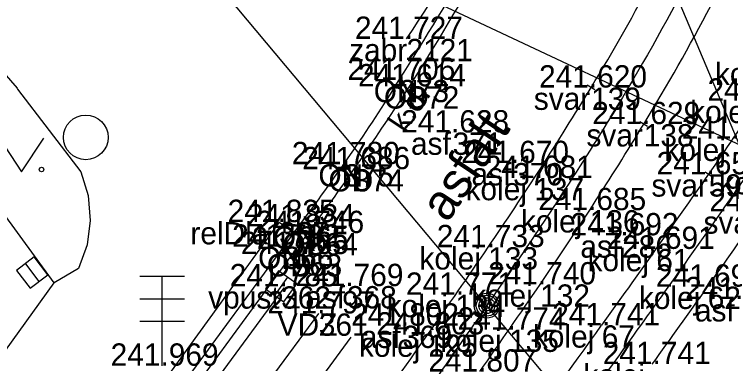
# Model space of a CAD drawing. Extents: x -599098 to -598820, y -1159597 to -1158744.
# Drawn here: x -598917.65 to -598901.61, y -1159373.2 to -1159365.37 of the extents above; entities that cross this region are included whole.
import ezdxf

# ---------------------------------------------------------------- set-up
doc = ezdxf.new("R2010")
doc.units = 0
for name, color, linetype in [('body', 7, 'Continuous'), ('dešťové vpusti šachty', 7, 'Continuous'), ('dopravní značky semafory', 7, 'Continuous'), ('druh pozemku stromy', 7, 'Continuous'), ('kresba', 7, 'Continuous'), ('kódy bodů', 7, 'Continuous'), ('popisy', 7, 'Continuous'), ('tram_detaily', 7, 'Continuous'), ('tram_koleje', 7, 'Continuous'), ('tram_osa', 7, 'Continuous'), ('trol_detaily', 7, 'Continuous'), ('trol_převěsy', 7, 'Continuous'), ('vodorovné dopravní značení_bílé', 7, 'Continuous'), ('výšky bodů', 7, 'Continuous'), ('značky IS', 7, 'Continuous'), ('zábradlí', 7, 'Continuous'), ('čísla bodů', 7, 'Continuous')]:
    doc.layers.add(name, color=color, linetype=linetype)

msp = doc.modelspace()

# ---------------------------------------------------------------- linework, layer by layer
at = {"layer": 'body'}
for p, q in [((-598908.871, -1159365.923), (-598908.871, -1159365.923)), ((-598909.033, -1159366.841), (-598909.033, -1159366.841)), ((-598908.803, -1159366.986), (-598908.803, -1159366.986)), ((-598904.736, -1159367.013), (-598904.736, -1159367.013)), ((-598903.558, -1159367.833), (-598903.558, -1159367.833)), ((-598907.837, -1159368.02), (-598907.837, -1159368.02)), ((-598906.482, -1159368.705), (-598906.482, -1159368.705)), ((-598910.272, -1159368.73), (-598910.272, -1159368.73)), ((-598910.045, -1159368.842), (-598910.045, -1159368.842)), ((-598902.103, -1159368.956), (-598902.103, -1159368.956)), ((-598906.008, -1159369.038), (-598906.008, -1159369.038)), ((-598904.768, -1159369.76), (-598904.768, -1159369.76)), ((-598911.722, -1159370.026), (-598911.722, -1159370.026)), ((-598911.292, -1159370.125), (-598911.292, -1159370.125)), ((-598911.074, -1159370.273), (-598911.074, -1159370.273)), ((-598904.044, -1159370.324), (-598904.044, -1159370.324)), ((-598911.622, -1159370.578), (-598911.622, -1159370.578)), ((-598907.04, -1159370.59), (-598907.04, -1159370.59)), ((-598903.277, -1159370.628), (-598903.277, -1159370.628)), ((-598911.425, -1159370.744), (-598911.425, -1159370.744)), ((-598905.877, -1159371.424), (-598905.877, -1159371.424)), ((-598911.675, -1159371.466), (-598911.675, -1159371.466)), ((-598910.203, -1159371.461), (-598910.203, -1159371.461)), ((-598902.126, -1159371.474), (-598902.126, -1159371.474)), ((-598907.774, -1159371.656), (-598907.774, -1159371.656)), ((-598910.833, -1159372.075), (-598910.833, -1159372.075)), ((-598908.959, -1159372.348), (-598908.959, -1159372.348)), ((-598904.5, -1159372.34), (-598904.5, -1159372.34)), ((-598908.394, -1159372.546), (-598908.394, -1159372.546)), ((-598906.574, -1159372.436), (-598906.574, -1159372.436))]:
    msp.add_line(p, q, dxfattribs=at)
at = {"layer": 'dešťové vpusti šachty'}
msp.add_line((-598911.821, -1159371.669), (-598911.529, -1159371.263), dxfattribs=at)
msp.add_lwpolyline([(-598911.618, -1159371.815), (-598911.326, -1159371.409), (-598911.732, -1159371.117), (-598912.024, -1159371.523)], close=True, dxfattribs=at)
at = {"layer": 'dopravní značky semafory'}
for p, q in [((-598913.842, -1159371.245), (-598914.842, -1159371.245)), ((-598914.342, -1159373.245), (-598914.342, -1159371.245)), ((-598914.842, -1159371.745), (-598913.842, -1159371.745)), ((-598914.842, -1159372.245), (-598913.842, -1159372.245))]:
    msp.add_line(p, q, dxfattribs=at)
at = {"layer": 'druh pozemku stromy'}
msp.add_lwpolyline([(-598917.99, -1159368.15), (-598917.49, -1159368.9), (-598916.99, -1159368.15)], dxfattribs=at)
msp.add_circle((-598917.041, -1159368.85), 0.05, dxfattribs=at)
at = {"layer": 'kresba'}
for p, q in [((-598917.58, -1159367.05), (-598916.16, -1159368.9)), ((-598911.722, -1159370.026), (-598915.873, -1159375.751)), ((-598911.722, -1159370.026), (-598911.393, -1159370.264)), ((-598911.292, -1159370.125), (-598911.622, -1159370.578)), ((-598911.425, -1159370.744), (-598911.074, -1159370.273)), ((-598911.622, -1159370.578), (-598914.322, -1159374.262)), ((-598914.091, -1159374.398), (-598911.425, -1159370.744))]:
    msp.add_line(p, q, dxfattribs=at)
for points in [[(-598919.1, -1159366.24), (-598918.51, -1159366.31), (-598917.99, -1159366.57), (-598917.59, -1159367.03), (-598917.58, -1159367.05)], [(-598937.39, -1159400.08), (-598916.76, -1159371.39), (-598918.73, -1159368.69)], [(-598916.16, -1159368.9), (-598916, -1159369.43), (-598915.95, -1159369.99), (-598916.02, -1159370.54), (-598916.21, -1159371.07), (-598916.76, -1159371.39)]]:
    msp.add_lwpolyline(points, dxfattribs=at)
for centre, radius, start, end in [((-598969.883, -1159328.28), 72.04, 327.63743, 330.28134), ((-598951.766, -1159339.58), 50.96, 327.4658, 331.2241), ((-598942.435, -1159346.283), 39.221, 322.564, 328.3893), ((-598958.726, -1159334.922), 59.333, 323.42989, 327.28864)]:
    msp.add_arc(centre, radius, start, end, dxfattribs=at)
at = {"layer": 'tram_detaily'}
for p, q in [((-598904.65, -1159367.064), (-598904.823, -1159366.963)), ((-598903.471, -1159367.883), (-598903.645, -1159367.782)), ((-598902.186, -1159368.9), (-598902.021, -1159369.013))]:
    msp.add_line(p, q, dxfattribs=at)
at = {"layer": 'tram_koleje'}
for centre, radius, start, end in [((-598942.625, -1159343.975), 44.343, 328.6991, 336.177), ((-598943.054, -1159343.749), 46.26, 328.6262, 336.1731), ((-598974.788, -1159324.422), 81.983, 325.72685, 328.70075), ((-599014.099, -1159291.363), 136.248, 325.28506, 326.12393), ((-598970.789, -1159326.961), 78.68, 325.58976, 328.70301), ((-599111.282, -1159223.328), 254.879, 324.22268, 325.1549), ((-599144.2, -1159199.597), 296.887, 324.21267, 325.02292), ((-599086.951, -1159247.497), 217.991, 324.99526, 325.62053), ((-599085.463, -1159248.483), 217.636, 324.98007, 325.60519), ((-600445.718, -1158261.326), 1899.922, 323.996025, 324.213389), ((-599082.727, -1159250.878), 212.591, 324.37258, 325.08858)]:
    msp.add_arc(centre, radius, start, end, dxfattribs=at)
at = {"layer": 'tram_osa'}
for points in [[(-598908.157, -1159378.609), (-598907.552, -1159377.778), (-598906.868, -1159376.836), (-598906.259, -1159375.995), (-598905.722, -1159375.252), (-598905.236, -1159374.581), (-598903.934, -1159372.775), (-598902.701, -1159371.051), (-598901.52, -1159369.371), (-598900.942, -1159368.531), (-598900.379, -1159367.695), (-598899.817, -1159366.835), (-598899.27, -1159365.964), (-598898.407, -1159364.472), (-598897.213, -1159362.023), (-598896.143, -1159359.185), (-598895.328, -1159356.139), (-598894.957, -1159354.036), (-598894.725, -1159351.774), (-598894.664, -1159349.708), (-598894.744, -1159347.678), (-598894.942, -1159345.779), (-598895.289, -1159343.649), (-598895.717, -1159341.566), (-598895.998, -1159340.38), (-598896.298, -1159339.199), (-598896.678, -1159337.758), (-598897.069, -1159336.322), (-598897.39, -1159335.158), (-598897.753, -1159333.858), (-598898.122, -1159332.54), (-598898.277, -1159331.985), (-598898.513, -1159331.142), (-598898.836, -1159329.985), (-598899.092, -1159329.068)], [(-598901.994, -1159329.852), (-598901.845, -1159330.39), (-598901.631, -1159331.17), (-598901.437, -1159331.875), (-598901.198, -1159332.751), (-598900.91, -1159333.821), (-598900.692, -1159334.638), (-598900.522, -1159335.294), (-598900.329, -1159336.063), (-598900.132, -1159336.868), (-598899.889, -1159337.918), (-598899.746, -1159338.571), (-598899.547, -1159339.551), (-598899.39, -1159340.382), (-598899.195, -1159341.532), (-598899.02, -1159342.683), (-598898.837, -1159344.035), (-598898.771, -1159344.588), (-598898.665, -1159345.59), (-598898.593, -1159346.409), (-598898.554, -1159347.04), (-598898.521, -1159347.953), (-598898.531, -1159349.751), (-598898.642, -1159351.517), (-598898.931, -1159353.817), (-598899.252, -1159355.498), (-598899.926, -1159358.17), (-598900.833, -1159360.806), (-598901.398, -1159362.161), (-598902.424, -1159364.327), (-598904.147, -1159367.423), (-598905.388, -1159369.399), (-598906.458, -1159371.007), (-598907.174, -1159372.046), (-598907.418, -1159372.398), (-598907.811, -1159372.961), (-598908.189, -1159373.5), (-598908.527, -1159373.98), (-598908.94, -1159374.563), (-598909.247, -1159374.993), (-598909.701, -1159375.623), (-598910.021, -1159376.065), (-598910.194, -1159376.303), (-598910.561, -1159376.808)]]:
    msp.add_spline(points, degree=3, dxfattribs=at)
at = {"layer": 'trol_detaily'}
for radius in [0.28, 0.235, 0.178, 0.118, 0.0641]:
    msp.add_circle((-598907.072, -1159371.9), radius, dxfattribs=at)
at = {"layer": 'trol_převěsy'}
for p, q in [((-598906.25, -1159356.79), (-598900.24, -1159371.111)), ((-598900.99, -1159379.16), (-598915.7, -1159361.6)), ((-598894.78, -1159371.42), (-598915.68, -1159361.59))]:
    msp.add_line(p, q, dxfattribs=at)
at = {"layer": 'vodorovné dopravní značení_bílé'}
for p, q in [((-598914.607, -1159375.572), (-598911.608, -1159371.5)), ((-598913.832, -1159376.147), (-598910.833, -1159372.075)), ((-598913.104, -1159376.676), (-598910.105, -1159372.604))]:
    msp.add_line(p, q, dxfattribs=at)
at = {"layer": 'značky IS'}
msp.add_line((-598917.403, -1159370.962), (-598917.1, -1159371.359), dxfattribs=at)
msp.add_lwpolyline([(-598917.601, -1159371.114), (-598917.298, -1159371.511), (-598916.9, -1159371.207), (-598917.205, -1159370.809)], close=True, dxfattribs=at)
msp.add_circle((-598916.05, -1159368.13), 0.5, dxfattribs=at)
at = {"layer": 'zábradlí'}
msp.add_arc((-598931.603, -1159350.423), 27.513, 325.7123, 341.6416, dxfattribs=at)

# ---------------------------------------------------------------- texts
at = {"layer": 'kódy bodů'}
for s, p in [('zabr', (-598910.154, -1159366.423)), ('kolej', (-598901.964, -1159366.958)), ('ON', (-598909.603, -1159367.341)), ('OD', (-598909.375, -1159367.486)), ('svar', (-598906.019, -1159367.513)), ('kolej', (-598902.519, -1159367.808)), ('asf', (-598908.77, -1159368.52)), ('svar', (-598904.841, -1159368.333)), ('kolej', (-598903.095, -1159368.659)), ('asf', (-598907.415, -1159369.205)), ('ON', (-598910.842, -1159369.23)), ('OD', (-598910.617, -1159369.342)), ('kolej', (-598907.548, -1159369.538)), ('kolej', (-598901.87, -1159369.404)), ('svar', (-598903.386, -1159369.456)), ('kolej', (-598906.308, -1159370.26)), ('svar', (-598902.22, -1159370.287)), ('relDla', (-598913.708, -1159370.526)), ('ON', (-598911.862, -1159370.625)), ('OD', (-598911.646, -1159370.773)), ('asf', (-598904.977, -1159370.824)), ('ON', (-598912.192, -1159371.078)), ('kolej', (-598908.58, -1159371.09)), ('kolej', (-598904.817, -1159371.128)), ('OD', (-598911.997, -1159371.244)), ('asf', (-598911.136, -1159371.961)), ('kolej', (-598907.417, -1159371.924)), ('vpust', (-598913.31, -1159371.966)), ('kolej', (-598903.666, -1159371.974)), ('kolej', (-598909.314, -1159372.156)), ('asf', (-598902.412, -1159372.254)), ('VDZ', (-598911.753, -1159372.575)), ('asf', (-598909.892, -1159372.848)), ('kolej', (-598906.04, -1159372.84)), ('kolej', (-598909.934, -1159373.046)), ('kolej', (-598908.114, -1159372.936)), ('kolej', (-598904.908, -1159373.71))]:
    msp.add_text(s, height=0.5, dxfattribs=at).set_placement(p)
at = {"layer": 'popisy'}
for s, height, rotation, p in [('k.o.', 0.5, 56.3821, (-598908.9, -1159368.049)), ('asfalt', 0.8, 56.1738, (-598907.952, -1159370.06))]:
    msp.add_text(s, height=height, rotation=rotation, dxfattribs=at).set_placement(p)
at = {"layer": 'výšky bodů'}
for s, p in [('241.727', (-598910.023, -1159365.923)), ('241.706', (-598910.193, -1159366.841)), ('241.614', (-598909.955, -1159366.986)), ('241.620', (-598905.902, -1159367.013)), ('241.608', (-598902.131, -1159367.308)), ('241.629', (-598904.71, -1159367.833)), ('241.628', (-598908.989, -1159368.02)), ('241.628', (-598902.707, -1159368.159)), ('241.780', (-598911.438, -1159368.73)), ('241.670', (-598907.648, -1159368.705)), ('241.686', (-598911.205, -1159368.842)), ('241.681', (-598907.116, -1159369.038)), ('241.650', (-598903.269, -1159368.956)), ('241.685', (-598905.92, -1159369.76)), ('241.655', (-598902.089, -1159369.787)), ('241.835', (-598912.874, -1159370.026)), ('241.834', (-598912.444, -1159370.125)), ('241.746', (-598912.234, -1159370.273)), ('241.692', (-598905.196, -1159370.324)), ('241.792', (-598912.774, -1159370.578)), ('241.733', (-598908.192, -1159370.59)), ('241.691', (-598904.385, -1159370.628)), ('241.765', (-598912.577, -1159370.744)), ('241.769', (-598911.355, -1159371.461)), ('241.740', (-598907.043, -1159371.424)), ('241.785', (-598912.827, -1159371.466)), ('241.696', (-598903.286, -1159371.474)), ('241.771', (-598908.882, -1159371.656)), ('241.678', (-598902.631, -1159371.754)), ('241.797', (-598911.985, -1159372.075)), ('241.802', (-598910.111, -1159372.348)), ('241.741', (-598905.608, -1159372.34)), ('241.803', (-598909.546, -1159372.546)), ('241.774', (-598907.726, -1159372.436)), ('241.741', (-598904.476, -1159373.21)), ('241.969', (-598915.494, -1159373.245)), ('241.807', (-598908.381, -1159373.376))]:
    msp.add_text(s, height=0.5, dxfattribs=at).set_placement(p)
at = {"layer": 'čísla bodů'}
for s, p in [('2121', (-598908.871, -1159366.423)), ('373', (-598909.033, -1159367.341)), ('372', (-598908.803, -1159367.486)), ('139', (-598904.736, -1159367.513)), ('138', (-598903.558, -1159368.333)), ('371', (-598907.837, -1159368.52)), ('370', (-598906.482, -1159369.205)), ('375', (-598910.272, -1159369.23)), ('374', (-598910.045, -1159369.342)), ('137', (-598906.008, -1159369.538)), ('59', (-598902.103, -1159369.456)), ('136', (-598904.768, -1159370.26)), ('367', (-598911.722, -1159370.526)), ('365', (-598911.292, -1159370.625)), ('364', (-598911.074, -1159370.773)), ('286', (-598904.044, -1159370.824)), ('366', (-598911.622, -1159371.078)), ('133', (-598907.04, -1159371.09)), ('61', (-598903.277, -1159371.128)), ('363', (-598911.425, -1159371.244)), ('132', (-598905.877, -1159371.924)), ('362', (-598911.675, -1159371.966)), ('368', (-598910.203, -1159371.961)), ('62', (-598902.126, -1159371.974)), ('134', (-598907.774, -1159372.156)), ('361', (-598910.833, -1159372.575)), ('369', (-598908.959, -1159372.848)), ('67', (-598904.5, -1159372.84)), ('125', (-598908.394, -1159373.046)), ('135', (-598906.574, -1159372.936))]:
    msp.add_text(s, height=0.5, dxfattribs=at).set_placement(p)

doc.saveas('drawing.dxf')
